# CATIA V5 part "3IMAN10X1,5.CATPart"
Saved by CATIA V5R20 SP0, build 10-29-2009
Part number: 3IMAN10X1,5
Revision: ANY
Definition: UNKNOWN
Nomenclature: 3IMAN10X1,5
Source: Unknown
Bounding box of the stored display mesh (mm): x -5 to 5, y 0 to 1.5, z -5 to 5
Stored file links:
  C:\Users\Utente\Desktop\IO LAVORO\3D X SITO CF\CUMSA\3D files CG\CG 864857\3IMAN10X1,5.CATPart
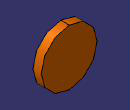
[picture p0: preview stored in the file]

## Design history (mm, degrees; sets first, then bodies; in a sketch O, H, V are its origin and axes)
Body1 "Saliente-Extruir1" (main body)
  Solid1: solid without history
